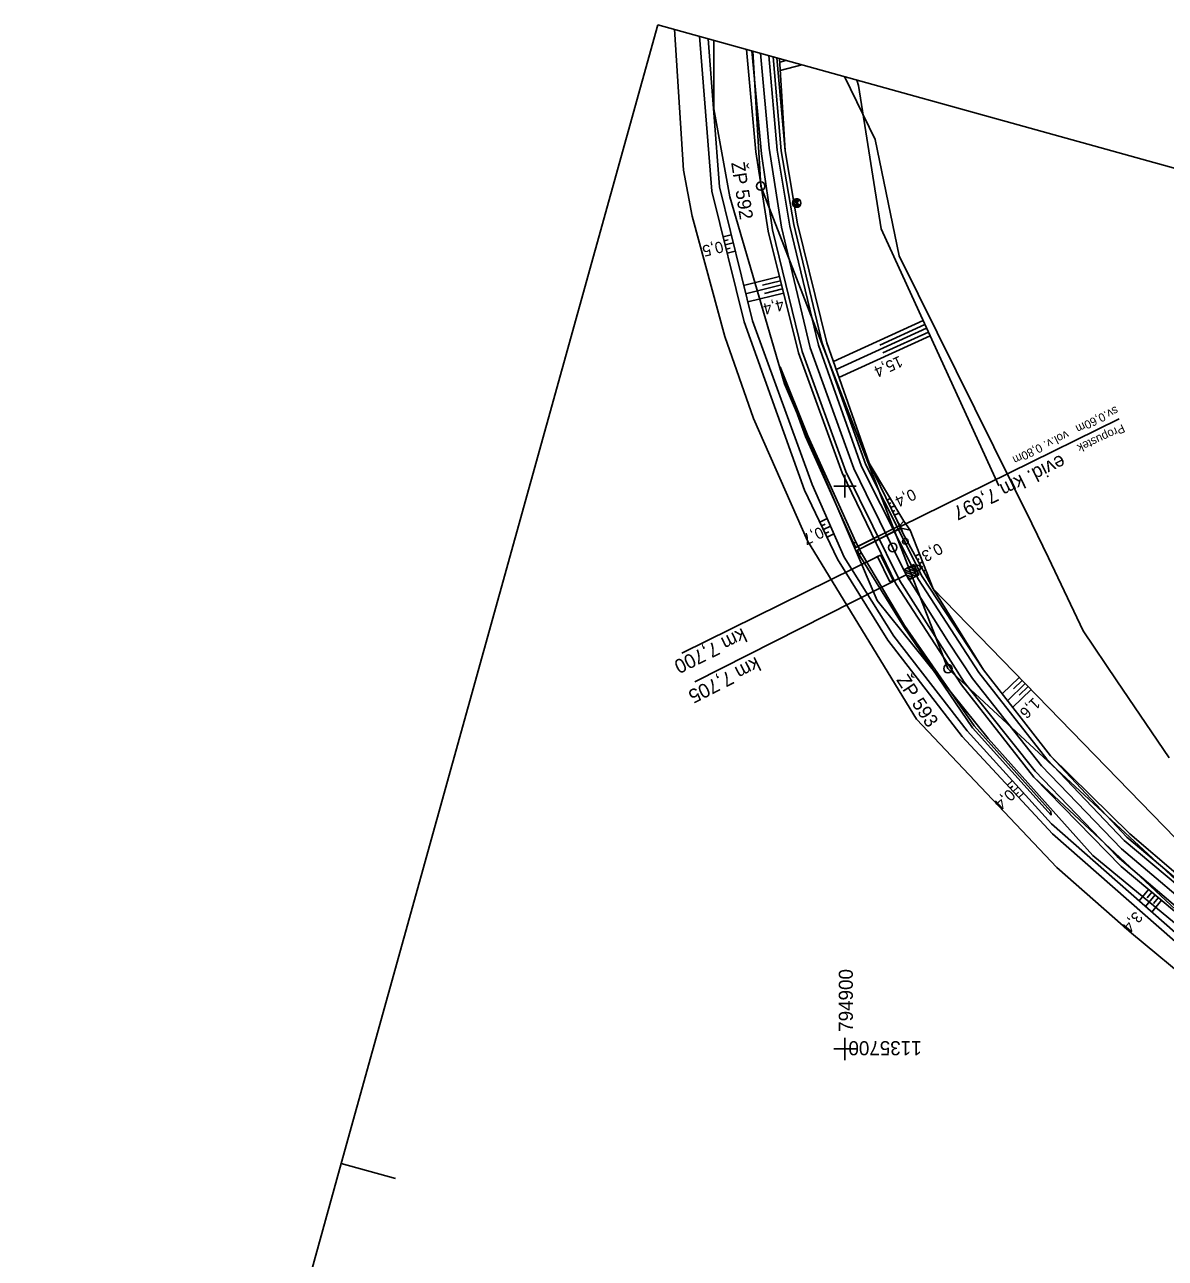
# Model space of a CAD drawing. Extents: x -795046 to -794647, y -1136002 to -1135518.
# Drawn here: x -795045.8 to -794843.1, y -1135737.2 to -1135518 of the extents above; entities that cross this region are included whole.
import ezdxf

# ---------------------------------------------------------------- set-up
doc = ezdxf.new("R2010")
doc.units = 0
for name, color, linetype in [('0381KM005-009P - Vrstva 1', 7, 'Continuous'), ('0381KM005-009P - Vrstva 13', 7, 'Continuous'), ('0381KM005-009P - Vrstva 19', 7, 'Continuous'), ('0381KM005-009P - Vrstva 28', 7, 'Continuous'), ('0381KM005-009P - Vrstva 3', 7, 'Continuous'), ('0381KM005-009P - Vrstva 4', 7, 'Continuous'), ('0381KM005-009P - Vrstva 48', 7, 'Continuous'), ('0381KM005-009P - Vrstva 49', 7, 'Continuous'), ('0381KM005-009P - Vrstva 51', 7, 'Continuous'), ('0381KM005-009P - Vrstva 55', 7, 'Continuous'), ('0381KM005-009P - Vrstva 7', 7, 'Continuous'), ('0381KM005-009P - Vrstva 9', 7, 'Continuous'), ('formát', 7, 'Continuous'), ('hran DP - hran DP', 7, 'Continuous'), ('krizky_1000 - souradnice', 7, 'Continuous'), ('krizky_1000 - Vrstva 1', 7, 'Continuous'), ('vyt_sit - polygon', 7, 'Continuous'), ('vyt_sit - stávající', 7, 'Continuous')]:
    doc.layers.add(name, color=color, linetype=linetype)

msp = doc.modelspace()

# ---------------------------------------------------------------- linework, layer by layer
at = {"layer": '0381KM005-009P - Vrstva 1'}
msp.add_lwpolyline([(-794915, -1135523.08), (-794913.46, -1135539.92), (-794911.29, -1135554.01), (-794906.18, -1135575.42), (-794898.43, -1135596.89), (-794896.25, -1135601.39), (-794889.11, -1135615.73), (-794881.58, -1135627.73), (-794877.36, -1135634.16), (-794865.05, -1135649.67), (-794850.87, -1135664.43), (-794835.06, -1135677.82), (-794817.77, -1135689.58), (-794801.57, -1135698.91), (-794785.04, -1135707.72), (-794765.11, -1135718.4), (-794746.17, -1135729.82), (-794729.27, -1135742.41), (-794716.02, -1135754.58), (-794701.99, -1135770.6), (-794697.2, -1135777.62)], dxfattribs=at)
at = {"layer": '0381KM005-009P - Vrstva 13'}
for points in [[(-794898.09, -1135609.93), (-794898.09, -1135609.93), (-794906.6, -1135591.05), (-794911.52, -1135578.79), (-794907, -1135591.18), (-794898.46, -1135610.15), (-794898.09, -1135609.93)], [(-794897.05, -1135611.89), (-794897.51, -1135612.1), (-794889.51, -1135624.97), (-794877.31, -1135642.92), (-794863.33, -1135658.49)], [(-794863.33, -1135658.49), (-794863.44, -1135657.81), (-794877.06, -1135642.57), (-794889.39, -1135624.78), (-794897.05, -1135611.89)]]:
    msp.add_lwpolyline(points, dxfattribs=at)
at = {"layer": '0381KM005-009P - Vrstva 19'}
for p, q in [((-794890.22, -1135607.23), (-794851.25, -1135588.05)), ((-794898.08, -1135610.9), (-794890.26, -1135606.98)), ((-794890.03, -1135607.47), (-794897.8, -1135611.38)), ((-794890.24, -1135606.98), (-794897.66, -1135610.68)), ((-794897.41, -1135611.19), (-794890.06, -1135607.43))]:
    msp.add_line(p, q, dxfattribs=at)
for points in [[(-794890.7, -1135606.17), (-794890.26, -1135606.98), (-794890.24, -1135606.98), (-794890.06, -1135607.43), (-794890.03, -1135607.47), (-794889.7, -1135608.37)], [(-794898.09, -1135609.93), (-794897.05, -1135611.89), (-794897.51, -1135612.1), (-794897.8, -1135611.38), (-794897.41, -1135611.19), (-794897.66, -1135610.68), (-794898.08, -1135610.9), (-794898.46, -1135610.15)]]:
    msp.add_lwpolyline(points, close=True, dxfattribs=at)
at = {"layer": '0381KM005-009P - Vrstva 28'}
msp.add_line((-794887.06, -1135614.6), (-794887.11, -1135614.51), dxfattribs=at)
msp.add_circle((-794887.08, -1135614.55), 0.5, dxfattribs=at)
at = {"layer": '0381KM005-009P - Vrstva 3'}
for p, q in [((-794889.11, -1135615.73), (-794926.66, -1135634.8)), ((-794886.88, -1135615.74), (-794889.56, -1135614.84)), ((-794887.35, -1135615.97), (-794889.32, -1135615.31)), ((-794887.11, -1135615.26), (-794889.08, -1135614.6)), ((-794887.83, -1135616.21), (-794889.08, -1135615.79)), ((-794888.3, -1135616.45), (-794888.85, -1135616.26)), ((-794887.35, -1135614.79), (-794888.61, -1135614.36)), ((-794887.58, -1135614.31), (-794888.13, -1135614.13))]:
    msp.add_line(p, q, dxfattribs=at)
msp.add_lwpolyline([(-794888.67, -1135616.63), (-794889.56, -1135614.84), (-794887.76, -1135613.95), (-794886.88, -1135615.74)], close=True, dxfattribs=at)
at = {"layer": '0381KM005-009P - Vrstva 4'}
for points in [[(-794917.47, -1135522.4), (-794915.85, -1135540.59), (-794913.67, -1135554.7), (-794908.27, -1135576.33), (-794900.49, -1135597.63), (-794890.98, -1135617.37), (-794879.27, -1135635.32), (-794866.44, -1135651.71), (-794836.69, -1135679.46), (-794818.84, -1135691.63), (-794786.57, -1135709.39), (-794766.3, -1135721.02), (-794748.58, -1135730.93), (-794731.42, -1135743.47), (-794717.51, -1135756.55), (-794703.68, -1135772.07), (-794698, -1135780.52)], [(-794697.72, -1135779.5), (-794703.02, -1135771.54), (-794717.11, -1135755.66), (-794731.12, -1135742.73), (-794748.15, -1135730.35), (-794763.88, -1135720.89), (-794786.11, -1135708.79), (-794818.08, -1135691.13), (-794836.08, -1135678.99), (-794851.61, -1135665.79), (-794866.22, -1135650.67), (-794878.82, -1135634.83), (-794890.24, -1135616.8), (-794899.85, -1135597.37), (-794907.59, -1135576.09), (-794912.87, -1135554.46), (-794914.85, -1135540.94), (-794916.58, -1135522.65)], [(-794696.7, -1135775.84), (-794700.88, -1135769.71), (-794714.51, -1135754.08), (-794728.76, -1135740.91), (-794743.23, -1135730.04), (-794762.73, -1135718.04), (-794783.1, -1135707.11), (-794816.84, -1135688.49), (-794833.24, -1135677.32), (-794850.38, -1135662.96), (-794864.1, -1135648.49), (-794876.22, -1135633.13), (-794886.94, -1135616.58), (-794897.05, -1135596.51), (-794904.69, -1135574.95), (-794909.82, -1135553.82), (-794912.02, -1135540.3), (-794913.51, -1135523.5)], [(-794912.74, -1135523.71), (-794911.32, -1135540.41), (-794909.07, -1135553.52), (-794904.05, -1135574.62), (-794896.27, -1135596.21), (-794886.26, -1135616.08), (-794875.38, -1135632.64), (-794863.5, -1135647.94), (-794849.93, -1135662.35), (-794832.65, -1135676.88), (-794816.85, -1135687.92), (-794782.78, -1135706.49), (-794762.23, -1135717.77), (-794742.47, -1135729.7), (-794727.73, -1135739.54), (-794713.83, -1135753.13), (-794700.2, -1135769.22), (-794696.4, -1135774.74)]]:
    msp.add_lwpolyline(points, dxfattribs=at)
at = {"layer": '0381KM005-009P - Vrstva 48'}
for p, q in [((-794910.48, -1135524.34), (-794911.58, -1135524.64)), ((-794907.65, -1135525.13), (-794911.49, -1135526.17)), ((-794921.65, -1135555.69), (-794920.21, -1135555.33)), ((-794921.47, -1135556.42), (-794920.75, -1135556.24)), ((-794921.29, -1135557.15), (-794919.85, -1135556.79)), ((-794921.11, -1135557.88), (-794920.39, -1135557.7)), ((-794920.93, -1135558.6), (-794919.5, -1135558.25)), ((-794911.66, -1135562.77), (-794918.01, -1135564.35)), ((-794911.47, -1135563.49), (-794914.65, -1135564.29)), ((-794911.29, -1135564.22), (-794917.65, -1135565.81)), ((-794910.93, -1135565.68), (-794917.29, -1135567.27)), ((-794911.11, -1135564.95), (-794914.29, -1135565.74)), ((-794886.1, -1135570.57), (-794902.06, -1135577.88)), ((-794885.48, -1135571.93), (-794901.56, -1135579.3)), ((-794885.79, -1135571.25), (-794893.8, -1135574.92)), ((-794884.85, -1135573.3), (-794901.06, -1135580.72)), ((-794885.17, -1135572.61), (-794893.24, -1135576.31)), ((-794892.51, -1135602.47), (-794891.95, -1135602.19)), ((-794892.18, -1135603.14), (-794891.87, -1135602.99)), ((-794891.85, -1135603.81), (-794891.18, -1135603.49)), ((-794891.52, -1135604.49), (-794891.16, -1135604.31)), ((-794891.19, -1135605.16), (-794890.41, -1135604.78)), ((-794904.48, -1135606.38), (-794903.16, -1135605.75)), ((-794904.16, -1135607.05), (-794903.51, -1135606.74)), ((-794903.83, -1135607.73), (-794902.56, -1135607.12)), ((-794903.51, -1135608.41), (-794902.89, -1135608.11)), ((-794903.19, -1135609.08), (-794901.96, -1135608.5)), ((-794887.47, -1135612.45), (-794886.76, -1135612.05)), ((-794887.11, -1135613.1), (-794886.8, -1135612.93)), ((-794886.75, -1135613.76), (-794886.2, -1135613.46)), ((-794886.39, -1135614.42), (-794886.16, -1135614.29)), ((-794886.03, -1135615.08), (-794885.64, -1135614.87)), ((-794869.01, -1135633.98), (-794872.05, -1135636.93)), ((-794867.96, -1135635.05), (-794871.12, -1135638.12)), ((-794868.48, -1135634.52), (-794870.03, -1135636.02)), ((-794867.44, -1135635.59), (-794869.05, -1135637.16)), ((-794866.92, -1135636.13), (-794870.2, -1135639.31)), ((-794871.13, -1135653.14), (-794870.27, -1135652.34)), ((-794870.62, -1135653.69), (-794870.19, -1135653.29)), ((-794870.11, -1135654.24), (-794869.27, -1135653.46)), ((-794869.6, -1135654.79), (-794869.18, -1135654.4)), ((-794869.09, -1135655.34), (-794868.26, -1135654.56)), ((-794846.02, -1135671.64), (-794847.73, -1135673.69)), ((-794844.87, -1135672.6), (-794846.61, -1135674.68)), ((-794845.45, -1135672.12), (-794846.31, -1135673.15)), ((-794844.3, -1135673.09), (-794845.17, -1135674.13)), ((-794843.72, -1135673.57), (-794845.48, -1135675.67))]:
    msp.add_line(p, q, dxfattribs=at)
at = {"layer": '0381KM005-009P - Vrstva 49'}
for p, q in [((-794912.11, -1135523.89), (-794910.64, -1135540.4)), ((-794890.7, -1135606.17), (-794890.26, -1135606.98)), ((-794890.26, -1135606.98), (-794889.55, -1135606.22)), ((-794890.03, -1135607.47), (-794888.43, -1135607.82)), ((-794889.7, -1135608.37), (-794890.03, -1135607.47))]:
    msp.add_line(p, q, dxfattribs=at)
for points in [[(-794925.83, -1135520.07), (-794923.66, -1135547.6), (-794917.9, -1135570.81), (-794907.19, -1135600.69), (-794901.33, -1135612.99), (-794892.4, -1135627.36), (-794879.19, -1135644.46), (-794863.1, -1135661.78), (-794838.91, -1135683.03), (-794815.97, -1135701.12), (-794794.79, -1135715.61), (-794782.46, -1135721.1), (-794767.75, -1135725.5), (-794750.75, -1135732.17), (-794732.98, -1135744.75), (-794719.14, -1135757.73), (-794705.45, -1135773.64), (-794699.07, -1135784.37)], [(-794749.75, -1135730.99), (-794767.46, -1135724.56), (-794782.23, -1135720.17), (-794794.11, -1135714.55), (-794814.96, -1135700.02), (-794837.43, -1135682.73), (-794863.32, -1135660), (-794878.31, -1135643.5), (-794891.31, -1135626.67), (-794900.17, -1135612.61), (-794905.81, -1135599.68), (-794916.46, -1135570.65), (-794922.29, -1135546.83), (-794924.31, -1135520.49)], [(-794917.47, -1135522.4), (-794915.85, -1135540.59), (-794913.67, -1135554.7), (-794908.27, -1135576.33), (-794900.49, -1135597.63), (-794890.98, -1135617.37), (-794879.27, -1135635.32), (-794866.44, -1135651.71), (-794850.9, -1135667.56)], [(-794911.62, -1135524.02), (-794910.64, -1135540.4), (-794908.42, -1135553.38), (-794903.23, -1135574.56), (-794895.71, -1135595.89), (-794889.55, -1135606.22), (-794888.43, -1135607.82), (-794884.32, -1135618.22)], [(-794897.87, -1135527.85), (-794897.6, -1135528.83), (-794893.57, -1135554.26), (-794872.65, -1135599.94)], [(-794895.71, -1135595.89), (-794890.7, -1135606.17)], [(-794889.7, -1135608.37), (-794884.32, -1135618.22), (-794824.85, -1135679.44), (-794811.36, -1135687.77), (-794786.09, -1135699.38), (-794707.09, -1135741.45)], [(-794863.5, -1135647.94), (-794875.38, -1135632.64), (-794884.32, -1135618.22)], [(-794695.93, -1135773.08), (-794698.78, -1135768.51), (-794712.94, -1135751.52), (-794727.73, -1135739.54), (-794743.72, -1135728.23), (-794763.92, -1135716.02), (-794781.48, -1135706.54), (-794800.89, -1135696.32), (-794816.57, -1135687.28), (-794832.17, -1135676.47), (-794849.4, -1135661.77), (-794863.5, -1135647.94)], [(-794850.9, -1135667.56), (-794836.69, -1135679.46), (-794818.84, -1135691.63), (-794803.16, -1135702.98), (-794784.32, -1135712.45), (-794768.51, -1135721.35), (-794758.17, -1135725.72), (-794749.71, -1135730.94)]]:
    msp.add_lwpolyline(points, dxfattribs=at)
at = {"layer": '0381KM005-009P - Vrstva 51'}
msp.add_lwpolyline([(-794699.07, -1135784.37), (-794705.45, -1135773.64), (-794719.14, -1135757.73), (-794732.98, -1135744.75), (-794750.75, -1135732.17), (-794767.75, -1135725.5), (-794782.46, -1135721.1), (-794794.79, -1135715.61), (-794815.97, -1135701.12), (-794838.91, -1135683.03), (-794863.1, -1135661.78), (-794879.19, -1135644.46), (-794892.4, -1135627.36), (-794901.33, -1135612.99), (-794907.19, -1135600.69), (-794917.9, -1135570.81), (-794923.66, -1135547.6), (-794925.83, -1135520.07)], dxfattribs=at)
at = {"layer": '0381KM005-009P - Vrstva 55'}
msp.add_lwpolyline([(-794930.32, -1135518.82), (-794928.69, -1135543.86), (-794927.18, -1135552.03), (-794921.37, -1135573.41), (-794916.26, -1135587.98), (-794906.67, -1135609.69), (-794887.27, -1135641.42), (-794862.33, -1135667.74), (-794849.1, -1135679.42), (-794837.63, -1135688.88), (-794826.42, -1135697.51), (-794808.25, -1135711.35), (-794792.02, -1135721.49), (-794781.13, -1135725.75), (-794765.57, -1135730.81), (-794749.96, -1135737.95), (-794742.14, -1135743.85), (-794737.72, -1135738.96), (-794727.83, -1135728.01), (-794718.43, -1135717.37), (-794692.54, -1135688.86), (-794715.68, -1135650.06)], dxfattribs=at)
at = {"layer": '0381KM005-009P - Vrstva 7'}
msp.add_line((-794889.24, -1135609.86), (-794889.28, -1135609.77), dxfattribs=at)
for centre, radius in [((-794889.26, -1135609.81), 0.5), ((-794891.51, -1135610.91), 0.75)]:
    msp.add_circle(centre, radius, dxfattribs=at)
at = {"layer": '0381KM005-009P - Vrstva 9'}
for p, q in [((-794893.93, -1135612.39), (-794929, -1135629.69)), ((-794894.19, -1135612.52), (-794894.73, -1135612.79)), ((-794893.66, -1135612.26), (-794894.19, -1135612.52)), ((-794894.19, -1135612.52), (-794892, -1135617.01)), ((-794891.46, -1135616.75), (-794893.66, -1135612.26)), ((-794892, -1135617.01), (-794891.46, -1135616.75))]:
    msp.add_line(p, q, dxfattribs=at)
at = {"layer": 'formát'}
for p, q in [((-794933.28, -1135518), (-794989.53, -1135720.33)), ((-794933.28, -1135518), (-794647.13, -1135597.56)), ((-794989.53, -1135720.33), (-795045.79, -1135922.65)), ((-794989.53, -1135720.33), (-794979.9, -1135723.01))]:
    msp.add_line(p, q, dxfattribs=at)
at = {"layer": 'hran DP - hran DP'}
for p, q in [((-794923.29, -1135532.94), (-794923.3, -1135520.77)), ((-794900.1, -1135527.22), (-794894.63, -1135538.4)), ((-794920.48, -1135548.58), (-794923.29, -1135532.94)), ((-794894.63, -1135538.4), (-794890.34, -1135559.06)), ((-794910.72, -1135581.84), (-794920.48, -1135548.58)), ((-794890.34, -1135559.06), (-794866.81, -1135606.62)), ((-794894.27, -1135620.34), (-794910.72, -1135581.84)), ((-794866.81, -1135606.62), (-794863.8, -1135612.72)), ((-794863.8, -1135612.72), (-794857.64, -1135625.71)), ((-794874.54, -1135644.85), (-794894.27, -1135620.34)), ((-794857.64, -1135625.71), (-794851.67, -1135634.62)), ((-794851.67, -1135634.62), (-794842.4, -1135648.25)), ((-794855.96, -1135665.64), (-794874.54, -1135644.85)), ((-794807.25, -1135705.8), (-794855.96, -1135665.64))]:
    msp.add_line(p, q, dxfattribs=at)
at = {"layer": 'krizky_1000 - Vrstva 1'}
for points in [[(-794900, -1135598), (-794900, -1135602)], [(-794902, -1135600), (-794898, -1135600)], [(-794900, -1135698), (-794900, -1135702)], [(-794902, -1135700), (-794898, -1135700)]]:
    msp.add_lwpolyline(points, dxfattribs=at)
at = {"layer": 'vyt_sit - polygon'}
for p, q in [((-794914.97, -1135546.67), (-794916.39, -1135522.7)), ((-794881.69, -1135632.43), (-794914.97, -1135546.67)), ((-794813.55, -1135695.63), (-794881.69, -1135632.43))]:
    msp.add_line(p, q, dxfattribs=at)
at = {"layer": 'vyt_sit - stávající'}
for p, q in [((-794914.98, -1135546.62), (-794914.96, -1135546.72)), ((-794908.58, -1135549.69), (-794909.2, -1135549.24)), ((-794908.46, -1135549.52), (-794909.05, -1135549.09)), ((-794909.02, -1135550.3), (-794908.58, -1135549.69)), ((-794908.4, -1135550.43), (-794908.87, -1135550.09)), ((-794908.28, -1135549.28), (-794908.74, -1135548.94)), ((-794908.1, -1135550.28), (-794908.69, -1135549.85)), ((-794908.13, -1135549.07), (-794908.58, -1135549.69)), ((-794908.58, -1135549.69), (-794907.96, -1135550.14)), ((-794881.72, -1135632.38), (-794881.67, -1135632.47))]:
    msp.add_line(p, q, dxfattribs=at)
for centre, radius in [((-794914.97, -1135546.67), 0.756), ((-794908.58, -1135549.69), 0.764), ((-794881.69, -1135632.43), 0.756)]:
    msp.add_circle(centre, radius, dxfattribs=at)
for radius, start, end in [(0.765, 53.9818, 143.8753), (0.764, 233.293, 323.611)]:
    msp.add_arc((-794908.58, -1135549.69), radius, start, end, dxfattribs=at)

# ---------------------------------------------------------------- texts
at = {"layer": '0381KM005-009P - Vrstva 19'}
for s, height, rotation, p in [('sv.0,60m   vol.v. 0,80m', 1.5, 206.2068, (-794851.86, -1135585.74)), ('Propustek', 1.5, 204.6627, (-794850.69, -1135588.94)), ('evid. km 7,697', 2.5, 206.2068, (-794861.56, -1135594.31))]:
    msp.add_text(s, height=height, rotation=rotation, dxfattribs=at).set_placement(p)
at = {"layer": '0381KM005-009P - Vrstva 3'}
msp.add_text('km 7,705', height=2.5, rotation=206.9201, dxfattribs=at).set_placement((-794915.82, -1135630.27))
at = {"layer": '0381KM005-009P - Vrstva 48'}
for s, rotation, p in [('0,5', 193.9485, (-794921.9, -1135556.44)), ('4,4', 194.0238, (-794911.11, -1135566.74)), ('15,4', 204.6063, (-794890.3, -1135576.77)), ('0,4', 205.994, (-794887.97, -1135600.39)), ('0,7', 205.5118, (-794904.35, -1135607.14)), ('0,3', 208.6712, (-794883.32, -1135610.02)), ('1,6', 224.1646, (-794866.45, -1135637.45)), ('0,4', 222.9053, (-794870.87, -1135653.69)), ('3,4', 230.0673, (-794848.42, -1135675.4))]:
    msp.add_text(s, height=2, rotation=rotation, dxfattribs=at).set_placement(p)
at = {"layer": '0381KM005-009P - Vrstva 9'}
msp.add_text('km 7,700', height=2.5, rotation=206.0861, dxfattribs=at).set_placement((-794918.25, -1135625.14))
at = {"layer": 'krizky_1000 - souradnice'}
for s, rotation, p in [('794900', 90, (-794898.6, -1135696.96)), ('1135700', 180, (-794886.37, -1135698.62))]:
    msp.add_text(s, height=2.5, rotation=rotation, dxfattribs=at).set_placement(p)
at = {"layer": 'vyt_sit - stávající'}
for s, rotation, p in [('ŽP 592', 278.77, (-794920.23, -1135542.54)), ('ŽP 593', 303.3346, (-794890.95, -1135634.44))]:
    msp.add_text(s, height=2.4, rotation=rotation, dxfattribs=at).set_placement(p)

doc.saveas('drawing.dxf')
